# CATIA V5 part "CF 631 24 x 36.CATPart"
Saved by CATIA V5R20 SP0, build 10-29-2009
Part number: CF 631 24 x 36
Definition: NONE
Nomenclature: CF 631 24 x 36
Source: Unknown
Description: CF 631 24 x 36
Bounding box of the stored display mesh (mm): x -13 to 23, y -22 to 22, z -22 to 22
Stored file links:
  C:\Users\Utente\Desktop\IO LAVORO\3D X SITO CF\X SITO\CF 631\CF 631 24 x 36.CATPart
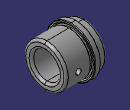
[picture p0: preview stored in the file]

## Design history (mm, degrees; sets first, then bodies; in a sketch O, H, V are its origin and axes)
Body1 "CF 631 24 x 36" (main body)
  Solid1: solid without history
